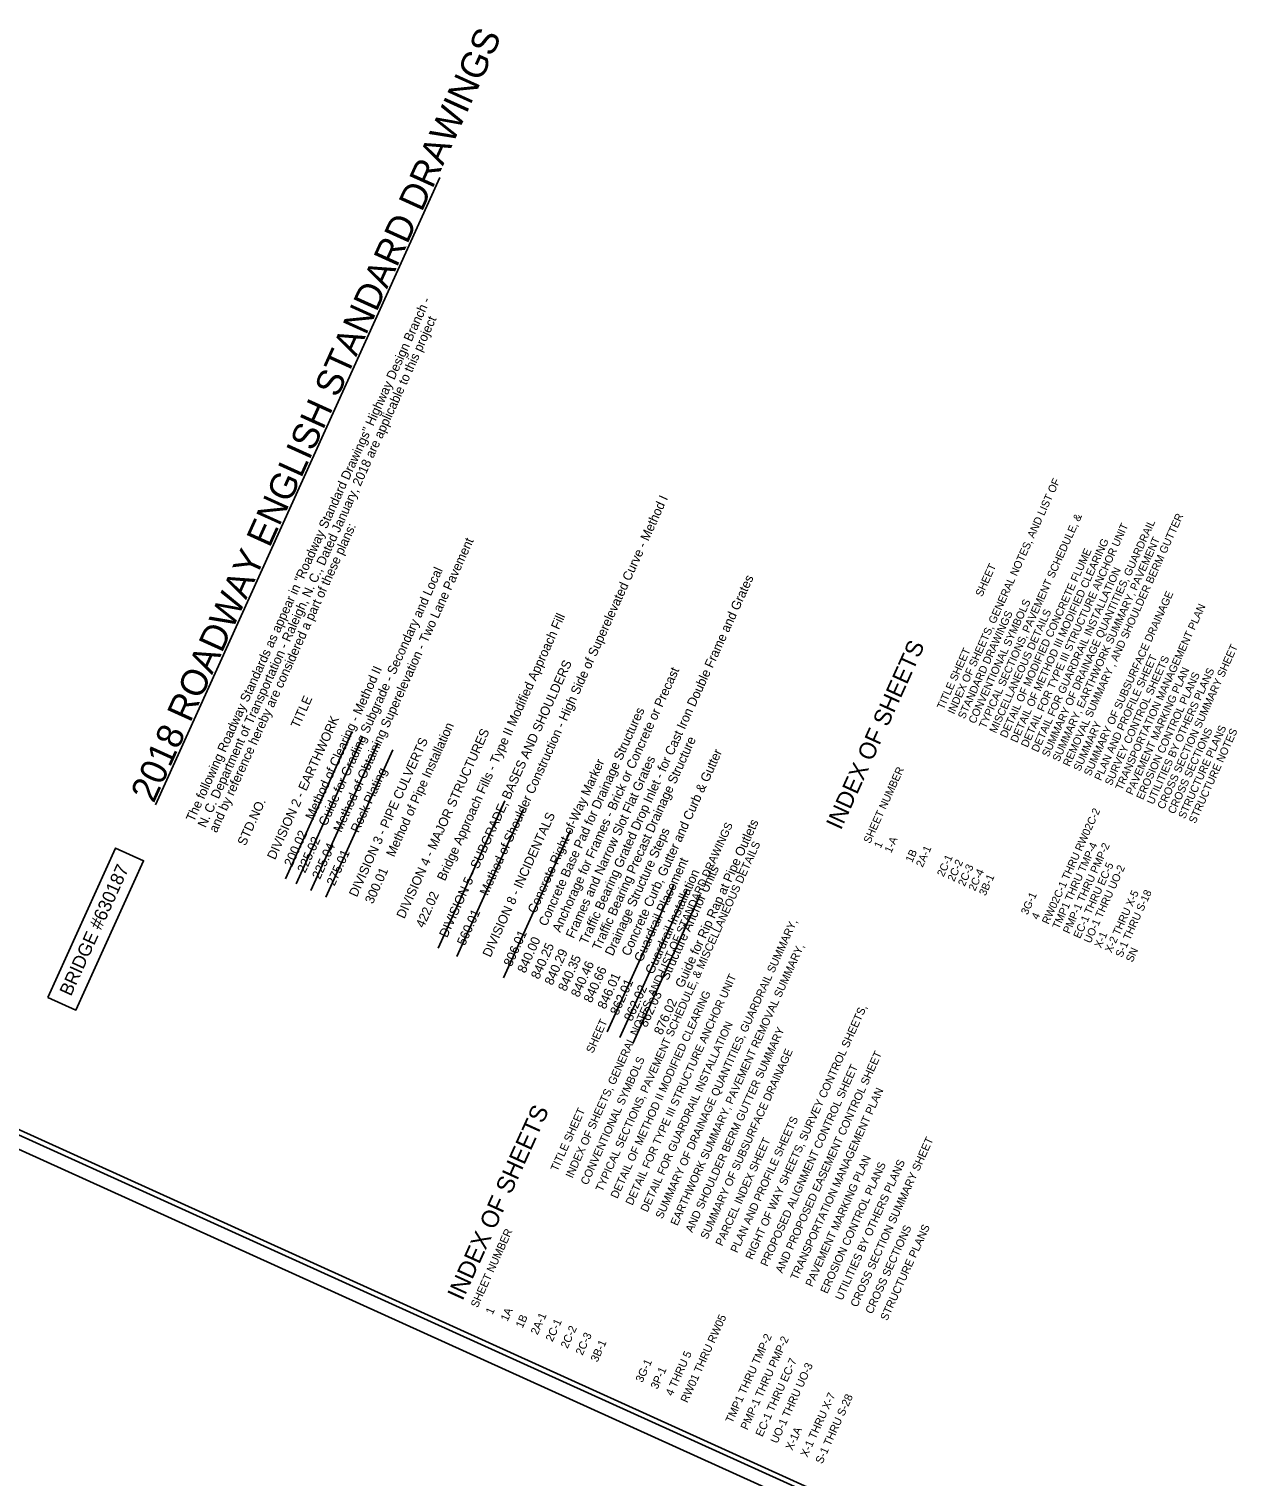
# Model space of a CAD drawing. Extents: x 1744741 to 2014229, y 466994 to 951338.
# Drawn here: x 2011483 to 2014057, y 477045 to 480129 of the extents above; entities that cross this region are included whole.
import ezdxf

# ---------------------------------------------------------------- set-up
doc = ezdxf.new("R2010")
doc.units = 0
for name, color, linetype in [('Old_Level_1', 7, 'Continuous'), ('Old_Level_34', 7, 'Continuous'), ('Prop Guardrail Anchor Unit CELL', 7, 'Continuous'), ('Sheet Plan CELL', 7, 'Continuous'), ('Sheet Plot Border Inside CELL', 7, 'Continuous'), ('Sheet Plot Border Outside CELL', 7, 'Continuous'), ('Sheet Sticker Preliminary CELL', 7, 'Continuous')]:
    doc.layers.add(name, color=color, linetype=linetype)

msp = doc.modelspace()

# ---------------------------------------------------------------- linework, layer by layer
at = {"layer": 'Old_Level_1'}
msp.add_line((2011753, 478475.7), (2012359, 479812.7), dxfattribs=at)
at = {"layer": 'Old_Level_34'}
msp.add_lwpolyline([(2011523.3, 478065), (2011667.6, 478383.3), (2011727.6, 478356.1), (2011583.3, 478037.8)], close=True, dxfattribs=at)
at = {"layer": 'Prop Guardrail Anchor Unit CELL'}
for p, q in [((2012029.8, 478317.4), (2012172.2, 478631.6)), ((2012052.4, 478307.2), (2012194.8, 478621.3)), ((2012084.1, 478292.8), (2012226.5, 478607)), ((2012115.8, 478278.4), (2012258.3, 478592.6)), ((2012355, 478170), (2012497.5, 478484.2)), ((2012394.9, 478151.9), (2012537.3, 478466.1)), ((2012494.6, 478106.8), (2012637, 478420.9)), ((2012715.4, 477991.4), (2012857.8, 478305.6)), ((2012742.5, 477979.1), (2012884.9, 478293.3)), ((2012769.7, 477966.8), (2012912.1, 478280.9))]:
    msp.add_line(p, q, dxfattribs=at)
at = {"layer": 'Sheet Plan CELL'}
msp.add_lwpolyline([(2011066.5, 477919.9), (2009673.2, 474845.9), (2011825, 473870.6), (2013218.3, 476944.6)], close=True, dxfattribs=at)
at = {"layer": 'Sheet Plot Border Inside CELL'}
msp.add_lwpolyline([(2011687.5, 473553.7), (2013235, 476967.9), (2011073, 477947.8), (2009525.5, 474533.7)], close=True, dxfattribs=at)
at = {"layer": 'Sheet Plot Border Outside CELL'}
msp.add_lwpolyline([(2011716.4, 473508.5), (2013280.2, 476958.5), (2011036.2, 477975.6), (2009472.4, 474525.6)], close=True, dxfattribs=at)

# ---------------------------------------------------------------- texts
at = {"layer": 'Old_Level_1'}
for s, height, p in [('422.02    Bridge Approach Fills - Type II Modified Approach Fill', 19.688, (2012324.3, 478211.7)), ('DIVISION 4 - MAJOR STRUCTURES', 19.688, (2012283.1, 478231.3)), ('BRIDGE #630187', 28.125, (2011572.7, 478065.9))]:
    msp.add_text(s, height=height, rotation=65.6171, dxfattribs=at).set_placement(p)
at = {"layer": 'Sheet Sticker Preliminary CELL'}
for s, height, p in [('2018 ROADWAY ENGLISH STANDARD DRAWINGS', 56.25, (2011749.1, 478477.3)), ('The following Roadway Standards as appear in "Roadway Standard Drawings" Highway Design Branch -', 19.688, (2011834.6, 478437.9)), ('N. C. Department of Transportation - Raleigh, N. C., Dated January, 2018 are applicable to this project', 19.6877, (2011859.6, 478425.3)), ('INDEX OF SHEETS, GENERAL NOTES, AND LIST OF ', 16.543, (2013454.4, 478667.3)), ('560.01     Method of Shoulder Construction - High Side of Superelevated Curve - Method I', 19.688, (2012412.1, 478173.9)), ('TYPICAL SECTIONS, PAVEMENT SCHEDULE, & ', 16.543, (2013521.5, 478636.9)), ('SUMMARY OF DRAINAGE QUANTITIES, GUARDRAIL ', 16.543, (2013655.6, 478576.1)), ('REMOVAL SUMMARY , AND SHOULDER BERM GUTTER ', 16.543, (2013700.3, 478555.8)), ('and by reference hereby are considered a part of these plans:', 19.688, (2011883.4, 478414.5)), ('DETAIL FOR TYPE III STRUCTURE ANCHOR UNIT', 16.543, (2013610.9, 478596.4)), ('SUMMARY, EARTHWORK SUMMARY, PAVEMENT ', 16.543, (2013677.9, 478566)), ('225.04    Method of Obtaining Superelevation - Two Lane Pavement', 19.688, (2012103.2, 478315.2)), ('DETAIL OF MODIFIED CONCRETE FLUME', 16.543, (2013566.2, 478616.6)), ('DETAIL OF METHOD III MODIFIED CLEARING', 16.543, (2013588.5, 478606.5)), ('SHEET', 16.54, (2013514, 478917.7)), ('225.02    Guide for Grading Subgrade - Secondary and Local', 19.688, (2012071.7, 478328.6)), ('840.35    Traffic Bearing Grated Drop Inlet - for Cast Iron Double Frame and Grates', 19.688, (2012627.3, 478076.4)), ('DETAIL FOR GUARDRAIL INSTALLATION', 16.543, (2013633.2, 478586.2)), ('SUMMARY OF SUBSURFACE DRAINAGE', 16.543, (2013745, 478535.6)), ('CONVENTIONAL SYMBOLS', 16.543, (2013499.1, 478647)), ('TRANSPORTATION MANAGEMENT PLAN', 16.543, (2013812.1, 478505.2)), ('STANDARD DRAWINGS', 16.543, (2013476.7, 478657.2)), ('MISCELLANEOUS DETAILS', 16.543, (2013543.8, 478626.8)), ('INDEX OF SHEETS', 36.094, (2013213.1, 478420)), ('TITLE SHEET', 16.543, (2013432, 478677.4)), ('CROSS SECTION SUMMARY SHEET', 16.543, (2013901.5, 478464.7)), ('200.02    Method of Clearing - Method II', 19.688, (2012043.8, 478341.9)), ('DIVISION 5 - SUBGRADE, BASES AND SHOULDERS', 19.688, (2012374.2, 478190.8)), ('840.25    Anchorage for Frames - Brick or Concrete or Precast', 19.688, (2012569.7, 478102.1)), ('PLAN AND PROFILE SHEET', 16.543, (2013767.3, 478525.5)), ('SURVEY CONTROL SHEETS', 16.543, (2013789.7, 478515.3)), ('PAVEMENT MARKING PLAN', 16.543, (2013834.4, 478495.1)), ('EROSION CONTROL PLANS', 16.543, (2013856.8, 478484.9)), ('UTILITIES BY OTHERS PLANS', 16.543, (2013879.1, 478474.8)), ('STD.NO.                       TITLE', 19.688, (2011944.4, 478386.6)), ('840.00    Concrete Base Pad for Drainage Structures', 19.688, (2012540.6, 478115.1)), ('DIVISION 2 - EARTHWORK', 19.688, (2012007.6, 478357)), ('300.01    Method of Pipe Installation ', 19.688, (2012215.9, 478262.8)), ('SUMMARY', 16.54, (2013722.6, 478545.7)), ('DIVISION 3 - PIPE CULVERTS', 19.688, (2012181.9, 478277.4)), ('840.46    Traffic Bearing Precast Drainage Structure', 19.688, (2012654.8, 478063.6)), ('CROSS SECTIONS', 16.543, (2013923.8, 478454.5)), ('STRUCTURE PLANS', 16.543, (2013946.2, 478444.4)), ('STRUCTURE NOTES', 16.543, (2013968.5, 478434.3)), ('846.01      Concrete Curb, Gutter and Curb & Gutter', 19.688, (2012711.3, 478038.2)), ('275.01      Rock Plating', 19.688, (2012134.2, 478301.1)), ('806.01      Concrete Right-of-Way Marker', 19.688, (2012511.4, 478129.1)), ('840.29    Frames and Narrow Slot Flat Grates', 19.688, (2012598.6, 478089.2)), ('SHEET NUMBER', 16.543, (2013275.6, 478391.7)), ('RW02C-1 THRU RW02C-2', 16.543, (2013655.6, 478219.4)), ('DIVISION 8 - INCIDENTALS', 19.688, (2012466.6, 478149)), ('INDEX OF SHEETS, GENERAL NOTES, AND LIST OF STANDARD DRAWINGS', 17.06, (2012641.2, 477678.2)), ('876.02    Guide for Rip Rap at Pipe Outlets', 19.688, (2012831.7, 477983.4)), ('840.66    Drainage Structure Steps', 19.688, (2012681.9, 478051.8)), ('1-A', 16.54, (2013320.3, 478371.4)), ('TYPICAL SECTIONS, PAVEMENT SCHEDULE, & MISCELLANEOUS DETAILS', 17.06, (2012705.1, 477649.3)), ('1', 16.5, (2013297.9, 478381.6)), ('1B', 16.54, (2013365, 478351.2)), ('2A-1', 16.54, (2013387.3, 478341)), ('TMP1 THRU TMP-4', 16.543, (2013677.9, 478209.3)), ('PMP-1 THRU PMP-2', 16.543, (2013700.3, 478199.2)), ('862.01      Guardrail Placement', 19.688, (2012738.1, 478025.4)), ('862.03    Structure Anchor Units', 19.688, (2012799.4, 477999.5)), ('2C-1', 16.54, (2013432.1, 478320.8)), ('2C-2', 16.54, (2013454.4, 478310.6)), ('2C-3', 16.54, (2013476.8, 478300.5)), ('2C-4', 16.54, (2013499.1, 478290.4)), ('EC-1 THRU EC-5', 16.543, (2013722.7, 478189)), ('UO-1 THRU UO-2', 16.543, (2013745, 478178.9)), ('862.02    Guardrail Installation', 19.688, (2012767.8, 478012.6)), ('3B-1', 16.54, (2013521.5, 478280.2)), ('3G-1', 16.54, (2013610.9, 478239.7)), ('X-2 THRU X-5', 16.543, (2013789.7, 478158.7)), ('S-1 THRU S-18', 16.543, (2013812.1, 478148.5)), ('4', 16.5, (2013633.2, 478229.6)), ('SUMMARY OF DRAINAGE QUANTITIES, GUARDRAIL SUMMARY, ', 17.06, (2012832.8, 477591.4)), ('X-1', 16.54, (2013767.4, 478168.8)), ('EARTHWORK SUMMARY, PAVEMENT REMOVAL SUMMARY, ', 17.06, (2012864.8, 477576.9)), ('SN', 16.54, (2013834.4, 478138.4)), ('DETAIL FOR TYPE III STRUCTURE ANCHOR UNIT', 17.06, (2012769, 477620.3)), ('DETAIL OF METHOD II MODIFIED CLEARING ', 17.06, (2012737, 477634.8)), ('RIGHT OF WAY SHEETS, SURVEY CONTROL SHEETS, ', 17.06, (2013024.4, 477504.5)), ('SHEET', 17.06, (2012684.9, 477944.5)), ('DETAIL FOR GUARDRAIL INSTALLATION', 17.06, (2012800.9, 477605.8)), ('AND SHOULDER BERM GUTTER SUMMARY', 17.06, (2012896.7, 477562.4)), ('CONVENTIONAL SYMBOLS', 17.06, (2012673.2, 477663.7)), ('SUMMARY OF SUBSURFACE DRAINAGE', 17.06, (2012928.6, 477547.9)), ('AND PROPOSED EASEMENT CONTROL SHEET', 17.06, (2013088.3, 477475.6)), ('PROPOSED ALIGNMENT CONTROL SHEET ', 17.06, (2013056.4, 477490)), ('TRANSPORTATION MANAGEMENT PLAN', 17.06, (2013120.2, 477461.1)), ('INDEX OF SHEETS', 37.222, (2012407.1, 477416.5)), ('TITLE SHEET', 17.06, (2012609.3, 477692.7)), ('PLAN AND PROFILE SHEETS', 17.06, (2012992.5, 477519)), ('PARCEL INDEX SHEET', 17.06, (2012960.6, 477533.5)), ('CROSS SECTION SUMMARY SHEET', 17.06, (2013248, 477403.2)), ('PAVEMENT MARKING PLAN', 17.06, (2013152.2, 477446.6)), ('EROSION CONTROL PLANS', 17.06, (2013184.1, 477432.1)), ('UTILITIES BY OTHERS PLANS', 17.06, (2013216, 477417.7)), ('SHEET NUMBER', 17.06, (2012439.1, 477402)), ('CROSS SECTIONS', 17.06, (2013279.9, 477388.7)), ('STRUCTURE PLANS', 17.06, (2013311.8, 477374.3)), ('1', 17.1, (2012471, 477387.6)), ('1A', 17.06, (2012502.9, 477373.1)), ('1B', 17.06, (2012534.9, 477358.6)), ('2A-1', 17.06, (2012566.8, 477344.1)), ('RW01 THRU RW05', 17.06, (2012886.1, 477199.4)), ('2C-1', 17.06, (2012598.7, 477329.7)), ('2C-2', 17.06, (2012630.7, 477315.2)), ('2C-3', 17.06, (2012662.6, 477300.7)), ('3B-1', 17.06, (2012694.5, 477286.2)), ('TMP1 THRU TMP-2', 17.06, (2012981.9, 477156)), ('PMP-1 THRU PMP-2', 17.06, (2013013.9, 477141.5)), ('3G-1', 17.06, (2012790.3, 477242.8)), ('4 THRU 5', 17.06, (2012854.2, 477213.9)), ('EC-1 THRU EC-7', 17.06, (2013045.8, 477127)), ('3P-1', 17.06, (2012822.3, 477228.3)), ('UO-1 THRU UO-3', 17.06, (2013077.7, 477112.6)), ('X-1 THRU X-7', 17.06, (2013141.6, 477083.6)), ('S-1 THRU S-28', 17.06, (2013173.5, 477069.1)), ('X-1A', 17.06, (2013109.7, 477098.1))]:
    msp.add_text(s, height=height, rotation=65.6171, dxfattribs=at).set_placement(p)

doc.saveas('drawing.dxf')
